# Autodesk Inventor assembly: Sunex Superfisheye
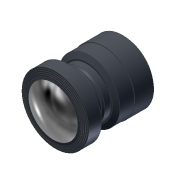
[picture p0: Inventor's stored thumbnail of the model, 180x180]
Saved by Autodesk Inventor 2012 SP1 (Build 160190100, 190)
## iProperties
Created: 2012-03
Part Number: Sunex Superfisheye
Document SubType Name: Assembly
Designer: jdh
Author: jdh
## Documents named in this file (3)
- C:\Documents and Settings\LACO\My Documents\Inventor\rainbow-camera-mount\06 imports\Sunex\Sunex Superfisheye.iam
- C:\Documents and Settings\LACO\My Documents\Inventor\rainbow-camera-mount\06 imports\Sunex\Sunex Superfisheye_mount.ipt
- C:\Documents and Settings\LACO\My Documents\Inventor\rainbow-camera-mount\06 imports\Sunex\Sunex Superfisheye_body.ipt
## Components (2 placed, 2 different names)
1. Sunex Superfisheye_mount:1 — Mate:1
2. Sunex Superfisheye_body:1 — Mate:1
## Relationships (1: Mate 1)
- Mate:1: Sunex Superfisheye_mount:1 ↔ Sunex Superfisheye_body:1
